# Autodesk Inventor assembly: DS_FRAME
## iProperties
Shininess: 64.0
Length Units: 11272
Angle Units: 11279
Time Units: 11290
Mass Units: 11286
Length Display Precision: 3
Angle Display Precision: 2
Compacted: True
Part Number: DS_FRAME
Document SubType Name: Assembly
Created: 2004-08
Designer: John Blackburn
Manufacturer: Standard
Standards Organization: Custom
Density: 0.0
Volumn: 0.0
Area: 0.0
PropertySet Name: Model Information
Control State: 0
Master: False
Checked Out: False
Author: John Blackburn
